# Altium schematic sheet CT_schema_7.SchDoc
size 287 x 160 mm
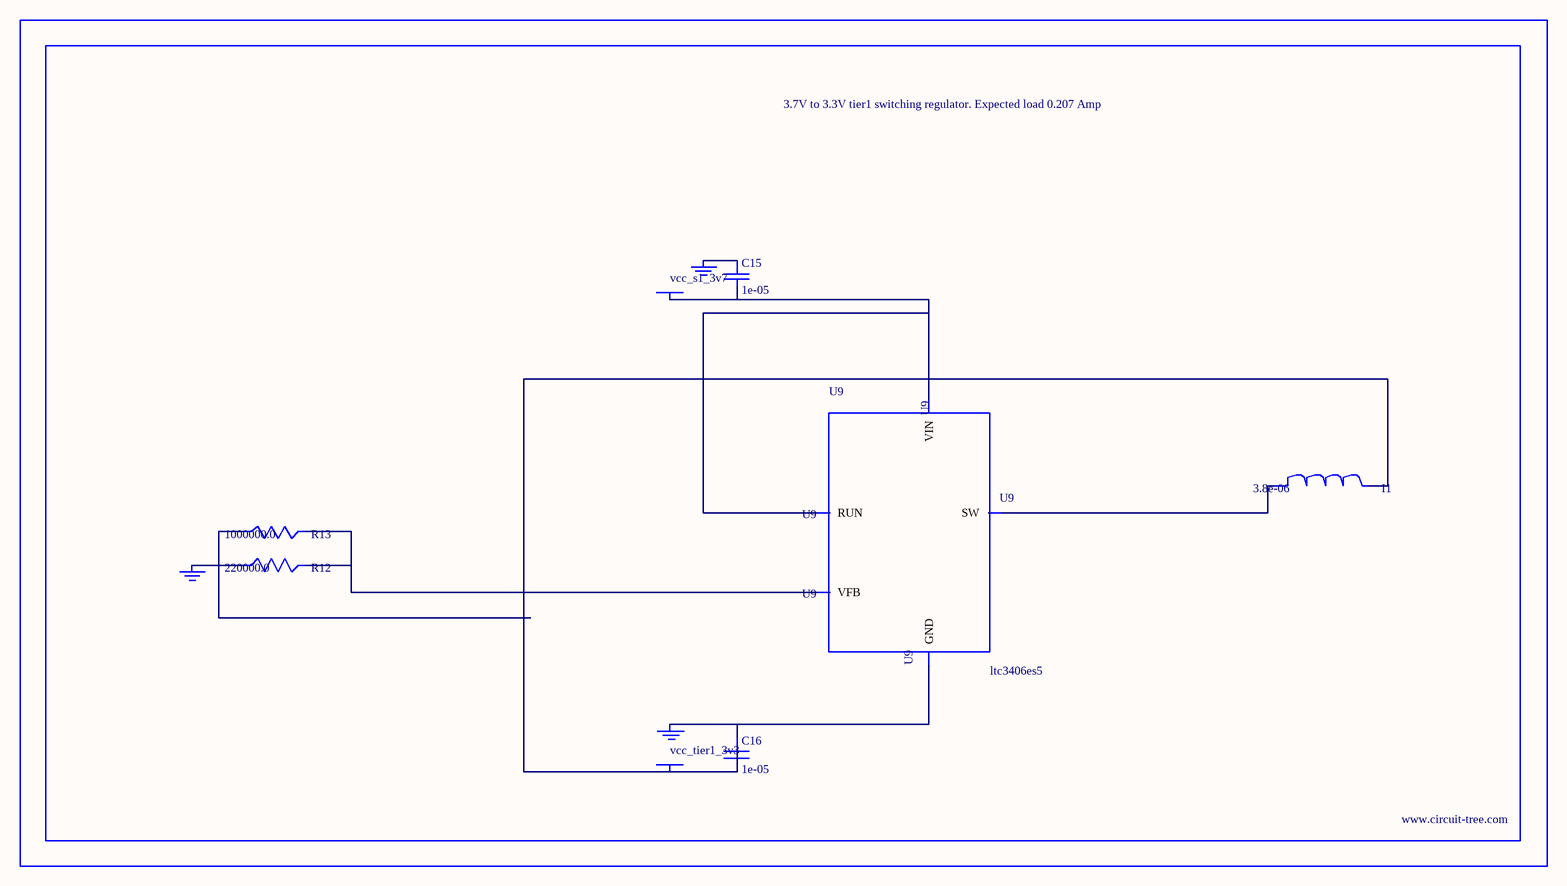
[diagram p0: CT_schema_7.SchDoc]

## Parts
BORDER6  (no value)
C15  1e-05  [C0805]
C16  1e-05  [C0805]
GND_INSTANCE_6_0  (no value)
GND_INSTANCE_6_1  (no value)
GND_INSTANCE_6_2  (no value)
I1  3.8e-06  [DR1040]
POWER_INSTANCE_6_0  vcc_tier1_3v3
POWER_INSTANCE_6_1  vcc_s1_3v7
R12  220000.0  [R0603]
R13  1000000.0  [R0603]
U9  ltc3406es5  [TSOT-23-5]

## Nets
NetC15_1: C15.1 GND_INSTANCE_6_1.0(GND)
NetC15_2: C15.2 POWER_INSTANCE_6_1.0(PWR) U9.1(RUN) U9.4(VIN)
NetC16_1: C16.1 GND_INSTANCE_6_0.0(GND) U9.2(GND)
NetC16_2: C16.2 I1.2 POWER_INSTANCE_6_0.0(PWR) R13.1
NetGND_INSTANCE_6_2_0: GND_INSTANCE_6_2.0(GND) R12.1
NetI1_1: I1.1 U9.3(SW)
NetR12_2: R12.2 R13.2 U9.5(VFB)

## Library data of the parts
BORDER6 = BORDER_PAGE6
C15 C16 = C0805C106K8RACTU
GND_INSTANCE_6_0-GND_INSTANCE_6_2 = GND
I1 = DR1040-3R8-R
POWER_INSTANCE_6_0 POWER_INSTANCE_6_1 = PWR
R12 = RC0603JR-07220KL
R13 = RC0603JR-071ML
